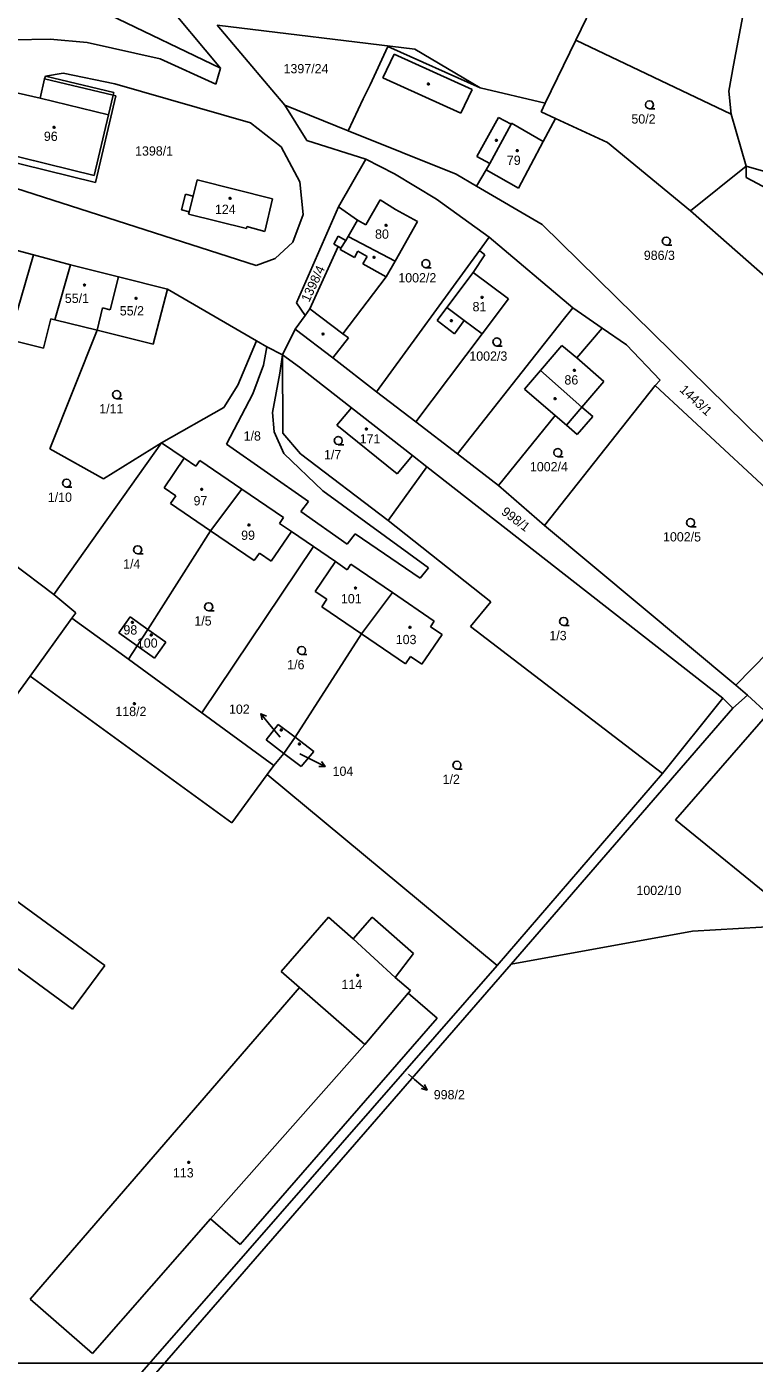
# Model space of a CAD drawing. Extents: x -852001 to -842497, y -1063614 to -1052182.
# Drawn here: x -849296.3 to -849163.1, y -1056500 to -1056255.4 of the extents above; entities that cross this region are included whole.
import ezdxf

# ---------------------------------------------------------------- set-up
doc = ezdxf.new("R2010")
doc.units = 0
for name, color, linetype in [('Default', 7, 'Continuous'), ('KLADY_ZMVM', 7, 'Continuous'), ('KN_HRANICE', 7, 'Continuous'), ('KN_KULTURY', 7, 'Continuous'), ('KN_PARCELY', 7, 'Continuous'), ('KN_SLUCKY', 7, 'Continuous')]:
    doc.layers.add(name, color=color, linetype=linetype)

# ---------------------------------------------------------------- blocks, each defined once
blk = doc.blocks.new('304')
at = {"layer": 'Default'}
blk.add_lwpolyline([(0, 0), (-0.38, 0.1), (-0.65, 0.37), (-0.75, 0.74), (-0.65, 1.11), (-0.38, 1.38), (-0.01, 1.48), (0.36, 1.38), (0.63, 1.11), (0.73, 0.73), (0.63, 0.35), (0.36, 0.08), (-0.02, -0.02), (0.98, -0.02)], dxfattribs=at)
blk = doc.blocks.new('NAHRADNI_SYMBOL')
at = {"layer": 'Default'}
blk.add_lwpolyline([(0.09, 0.15), (0.18, 0), (0.09, -0.15), (-0.09, -0.15), (-0.18, 0), (-0.09, 0.15), (0.09, 0.15)], dxfattribs=at)
blk = doc.blocks.new('10292')
at = {"layer": 'Default'}
blk.add_line((0, 3), (0, 0), dxfattribs=at)
blk.add_lwpolyline([(-0.5, 2), (0, 3), (0.5, 2)], dxfattribs=at)
blk = doc.blocks.new('402')
at = {"layer": 'Default'}
blk.add_lwpolyline([(0.09, 0.15), (0.18, 0), (0.09, -0.15), (-0.09, -0.15), (-0.18, 0), (-0.09, 0.15), (0.09, 0.15)], dxfattribs=at)

msp = doc.modelspace()

# ---------------------------------------------------------------- linework, layer by layer
at = {"layer": 'KLADY_ZMVM'}
msp.add_lwpolyline([(-849375, -1056500), (-848750, -1056500), (-848750, -1056000)], dxfattribs=at)
at = {"layer": 'KN_HRANICE'}
for p, q in [((-849279.99, -1056240.09), (-849260.83, -1056263.03)), ((-849187.73, -1056241.12), (-849195.81, -1056257.87)), ((-849166.92, -1056262.43), (-849164.8, -1056251.16)), ((-849281.15, -1056253.26), (-849260.83, -1056263.03)), ((-849261.46, -1056255.12), (-849257.13, -1056260.24)), ((-849261.46, -1056255.12), (-849225.25, -1056259.54)), ((-849298.81, -1056257.8), (-849292.01, -1056257.69)), ((-849292.01, -1056257.69), (-849285.23, -1056258.34)), ((-849285.23, -1056258.34), (-849271.88, -1056261.33)), ((-849257.13, -1056260.24), (-849251.43, -1056266.98)), ((-849230.23, -1056259.07), (-849233.42, -1056266.05)), ((-849230.23, -1056259.07), (-849213.31, -1056266.59)), ((-849225.25, -1056259.54), (-849213.31, -1056266.59)), ((-849195.81, -1056257.87), (-849201.39, -1056269.43)), ((-849195.81, -1056257.87), (-849167.34, -1056271.45)), ((-849271.88, -1056261.33), (-849261.72, -1056265.96)), ((-849167.78, -1056267.19), (-849166.92, -1056262.43)), ((-849293.85, -1056268.49), (-849293.05, -1056264.93)), ((-849292.89, -1056264.47), (-849293.05, -1056264.93)), ((-849292.89, -1056264.47), (-849289.64, -1056263.9)), ((-849280.38, -1056267.45), (-849292.89, -1056264.47)), ((-849289.64, -1056263.9), (-849280.17, -1056265.87)), ((-849261.72, -1056265.96), (-849260.83, -1056263.03)), ((-849297.86, -1056267.56), (-849293.85, -1056268.49)), ((-849280.52, -1056267.92), (-849280.38, -1056267.45)), ((-849280.17, -1056265.87), (-849255.38, -1056273.01)), ((-849251.43, -1056266.98), (-849249.09, -1056269.78)), ((-849233.42, -1056266.05), (-849234.71, -1056268.6)), ((-849201.39, -1056269.43), (-849213.31, -1056266.59)), ((-849167.34, -1056271.45), (-849167.78, -1056267.19)), ((-849283.7, -1056283.9), (-849280.01, -1056268.08)), ((-849280.01, -1056268.08), (-849280.52, -1056267.92)), ((-849249.09, -1056269.78), (-849245.03, -1056276.25)), ((-849249.09, -1056269.78), (-849237.45, -1056274.45)), ((-849234.71, -1056268.6), (-849237.45, -1056274.45)), ((-849201.39, -1056269.43), (-849202.16, -1056271.02)), ((-849202.16, -1056271.02), (-849199.51, -1056272.24)), ((-849201.75, -1056276.45), (-849199.51, -1056272.24)), ((-849199.51, -1056272.24), (-849189.99, -1056276.6)), ((-849167.34, -1056271.45), (-849164.6, -1056280.95)), ((-849255.38, -1056273.01), (-849249.72, -1056277.39)), ((-849237.45, -1056274.45), (-849217.67, -1056282.38)), ((-849249.72, -1056277.39), (-849246.35, -1056283.83)), ((-849245.03, -1056276.25), (-849234.23, -1056279.63)), ((-849206.29, -1056284.99), (-849201.75, -1056276.45)), ((-849189.99, -1056276.6), (-849174.78, -1056289.12)), ((-849254.33, -1056299.1), (-849321.06, -1056277.69)), ((-849307.26, -1056278.16), (-849283.7, -1056283.9)), ((-849239.22, -1056288.41), (-849234.23, -1056279.63)), ((-849234.23, -1056279.63), (-849228.99, -1056282.32)), ((-849228.99, -1056282.32), (-849221.32, -1056287)), ((-849213.98, -1056284.6), (-849212.18, -1056281.64)), ((-849212.18, -1056281.64), (-849206.29, -1056284.99)), ((-849174.78, -1056289.12), (-849164.6, -1056280.95)), ((-849164.6, -1056280.95), (-849143.72, -1056286.9)), ((-849164.6, -1056280.95), (-849164.59, -1056283.02)), ((-849265.86, -1056286.42), (-849265.11, -1056283.46)), ((-849265.11, -1056283.46), (-849251.31, -1056286.91)), ((-849246.35, -1056283.83), (-849245.71, -1056289.79)), ((-849217.67, -1056282.38), (-849213.98, -1056284.6)), ((-849213.98, -1056284.6), (-849201.97, -1056291.61)), ((-849150.22, -1056290.7), (-849164.59, -1056283.02)), ((-849267.99, -1056288.94), (-849267.27, -1056286.07)), ((-849267.27, -1056286.07), (-849265.86, -1056286.42)), ((-849252.72, -1056292.88), (-849251.31, -1056286.91)), ((-849231.64, -1056287.13), (-849234.22, -1056291.69)), ((-849231.64, -1056287.13), (-849228.79, -1056288.86)), ((-849221.32, -1056287), (-849211.67, -1056293.94)), ((-849266.58, -1056289.3), (-849267.99, -1056288.94)), ((-849266.69, -1056289.75), (-849266.58, -1056289.3)), ((-849246.94, -1056305.93), (-849239.22, -1056288.41)), ((-849239.22, -1056288.41), (-849235.78, -1056290.81)), ((-849228.79, -1056288.86), (-849224.8, -1056291.07)), ((-849174.78, -1056289.12), (-849146.16, -1056314.38)), ((-849266.69, -1056289.75), (-849256.11, -1056292.32)), ((-849256.11, -1056292.32), (-849256.03, -1056292)), ((-849256.03, -1056292), (-849252.72, -1056292.88)), ((-849245.71, -1056289.79), (-849247.6, -1056294.83)), ((-849237.48, -1056293.82), (-849235.78, -1056290.81)), ((-849234.22, -1056291.69), (-849235.78, -1056290.81)), ((-849224.8, -1056291.07), (-849228.88, -1056298.35)), ((-849161.41, -1056331.37), (-849201.97, -1056291.61)), ((-849240.1, -1056295.2), (-849239.29, -1056293.78)), ((-849239.29, -1056293.78), (-849237.9, -1056294.56)), ((-849237.9, -1056294.56), (-849237.48, -1056293.82)), ((-849211.67, -1056293.94), (-849213.44, -1056296.36)), ((-849211.67, -1056293.94), (-849196.32, -1056306.88)), ((-849295.08, -1056297.16), (-849299.89, -1056295.86)), ((-849247.6, -1056294.83), (-849250.85, -1056297.85)), ((-849244.48, -1056307.03), (-849239.28, -1056295.66)), ((-849240.1, -1056295.2), (-849239.28, -1056295.66)), ((-849213.44, -1056296.36), (-849232.27, -1056322.21)), ((-849212.44, -1056297.19), (-849213.44, -1056296.36)), ((-849288.31, -1056299), (-849295.08, -1056297.16)), ((-849291.17, -1056309.06), (-849288.31, -1056299)), ((-849288.31, -1056299), (-849279.52, -1056301.18)), ((-849250.85, -1056297.85), (-849254.33, -1056299.1)), ((-849228.88, -1056298.35), (-849230.49, -1056301.22)), ((-849214.56, -1056300.37), (-849212.44, -1056297.19)), ((-849281.07, -1056307.24), (-849279.52, -1056301.18)), ((-849279.52, -1056301.18), (-849270.57, -1056303.47)), ((-849230.49, -1056301.22), (-849238.43, -1056311.61)), ((-849208.12, -1056305.21), (-849214.56, -1056300.37)), ((-849270.57, -1056303.47), (-849273.15, -1056313.52)), ((-849270.57, -1056303.47), (-849254.26, -1056312.92)), ((-849246.94, -1056305.93), (-849245.37, -1056308.26)), ((-849208.12, -1056305.21), (-849212.96, -1056311.65)), ((-849293.26, -1056314.27), (-849291.9, -1056308.87)), ((-849291.9, -1056308.87), (-849291.17, -1056309.06)), ((-849283.45, -1056310.97), (-849291.17, -1056309.06)), ((-849283.45, -1056310.97), (-849282.44, -1056306.89)), ((-849282.44, -1056306.89), (-849281.07, -1056307.24)), ((-849247.18, -1056310.75), (-849245.37, -1056308.26)), ((-849245.37, -1056308.26), (-849244.48, -1056307.03)), ((-849217.45, -1056333.6), (-849198.14, -1056309.07)), ((-849196.32, -1056306.88), (-849198.14, -1056309.07)), ((-849190.95, -1056310.59), (-849196.32, -1056306.88)), ((-849310.53, -1056309.9), (-849293.26, -1056314.27)), ((-849292.1, -1056332.65), (-849283.45, -1056310.97)), ((-849273.15, -1056313.52), (-849283.45, -1056310.97)), ((-849249.52, -1056315.45), (-849247.18, -1056310.75)), ((-849240.27, -1056316.03), (-849247.18, -1056310.75)), ((-849238.43, -1056311.61), (-849237.42, -1056312.38)), ((-849212.96, -1056311.65), (-849225.06, -1056327.75)), ((-849195.6, -1056316.01), (-849190.95, -1056310.59)), ((-849186.5, -1056313.66), (-849190.95, -1056310.59)), ((-849254.26, -1056312.92), (-849257.7, -1056321.02)), ((-849254.26, -1056312.92), (-849252.37, -1056314.02)), ((-849252.95, -1056317.34), (-849252.37, -1056314.02)), ((-849252.37, -1056314.02), (-849249.52, -1056315.45)), ((-849237.42, -1056312.38), (-849240.27, -1056316.03)), ((-849180.36, -1056320.1), (-849186.5, -1056313.66)), ((-849249.52, -1056315.45), (-849250, -1056318.83)), ((-849249.41, -1056329.82), (-849249.52, -1056315.45)), ((-849249.52, -1056315.45), (-849246.38, -1056317.74)), ((-849232.27, -1056322.21), (-849240.27, -1056316.03)), ((-849195.6, -1056316.01), (-849190.65, -1056320.37)), ((-849254.93, -1056322.6), (-849252.95, -1056317.34)), ((-849250, -1056318.83), (-849251.32, -1056325.99)), ((-849246.38, -1056317.74), (-849236.86, -1056325.16)), ((-849257.7, -1056321.02), (-849260.26, -1056325.11)), ((-849201.5, -1056346.7), (-849181.26, -1056321.09)), ((-849194.67, -1056325.05), (-849190.65, -1056320.37)), ((-849181.26, -1056321.09), (-849180.36, -1056320.1)), ((-849181.26, -1056321.09), (-849145.42, -1056354.4)), ((-849259.75, -1056331.81), (-849254.93, -1056322.6)), ((-849225.06, -1056327.75), (-849232.27, -1056322.21)), ((-849260.26, -1056325.11), (-849271.64, -1056331.55)), ((-849251.32, -1056325.99), (-849251.01, -1056329.53)), ((-849239.52, -1056328.34), (-849236.86, -1056325.16)), ((-849236.86, -1056325.16), (-849225.69, -1056333.89)), ((-849194.67, -1056325.05), (-849192.7, -1056326.75)), ((-849228.48, -1056337.23), (-849239.52, -1056328.34)), ((-849217.45, -1056333.6), (-849225.06, -1056327.75)), ((-849209.96, -1056339.35), (-849199.56, -1056326.59)), ((-849197.51, -1056328.35), (-849199.56, -1056326.59)), ((-849195.53, -1056330.05), (-849197.51, -1056328.35)), ((-849192.7, -1056326.75), (-849195.53, -1056330.05)), ((-849251.01, -1056329.53), (-849249.23, -1056333.55)), ((-849246.19, -1056333.59), (-849249.41, -1056329.82)), ((-849282.25, -1056338.14), (-849292.1, -1056332.65)), ((-849291.34, -1056359.34), (-849271.64, -1056331.55)), ((-849271.64, -1056331.55), (-849282.25, -1056338.14)), ((-849271.64, -1056331.55), (-849267.48, -1056334.39)), ((-849244.73, -1056342.28), (-849259.75, -1056331.81)), ((-849249.23, -1056333.55), (-849242.11, -1056340.33)), ((-849230.16, -1056345.77), (-849246.19, -1056333.59)), ((-849209.96, -1056339.35), (-849217.45, -1056333.6)), ((-849267.48, -1056334.39), (-849271.16, -1056339.78)), ((-849265.33, -1056335.85), (-849267.48, -1056334.39)), ((-849264.6, -1056334.81), (-849265.33, -1056335.85)), ((-849264.6, -1056334.81), (-849256.96, -1056340.03)), ((-849223.07, -1056335.94), (-849230.16, -1056345.77)), ((-849225.69, -1056333.89), (-849228.48, -1056337.23)), ((-849223.07, -1056335.94), (-849225.69, -1056333.89)), ((-849223.07, -1056335.94), (-849168.88, -1056378.32)), ((-849271.16, -1056339.78), (-849269.01, -1056341.24)), ((-849262.65, -1056347.66), (-849256.96, -1056340.03)), ((-849256.96, -1056340.03), (-849249.3, -1056345.26)), ((-849242.11, -1056340.33), (-849222.76, -1056354.44)), ((-849201.5, -1056346.7), (-849209.96, -1056339.35)), ((-849269.01, -1056341.24), (-849269.98, -1056342.65)), ((-849269.98, -1056342.65), (-849262.65, -1056347.66)), ((-849246.11, -1056344.16), (-849244.73, -1056342.28)), ((-849250.02, -1056346.33), (-849249.3, -1056345.26)), ((-849237.68, -1056350.14), (-849246.11, -1056344.16)), ((-849230.16, -1056345.77), (-849211.36, -1056360.66)), ((-849262.65, -1056347.66), (-849274.12, -1056365.74)), ((-849262.65, -1056347.66), (-849254.67, -1056353.12)), ((-849251.57, -1056353.21), (-849247.87, -1056347.82)), ((-849247.87, -1056347.82), (-849250.02, -1056346.33)), ((-849243.84, -1056350.56), (-849247.87, -1056347.82)), ((-849236.2, -1056348.24), (-849237.68, -1056350.14)), ((-849224.27, -1056356.34), (-849236.2, -1056348.24)), ((-849201.5, -1056346.7), (-849166.49, -1056375.89)), ((-849264.25, -1056380.97), (-849243.84, -1056350.56)), ((-849243.84, -1056350.56), (-849239.82, -1056353.29)), ((-849254.67, -1056353.12), (-849253.72, -1056351.73)), ((-849253.72, -1056351.73), (-849251.57, -1056353.21)), ((-849291.34, -1056359.34), (-849299.09, -1056353.44)), ((-849239.82, -1056353.29), (-849243.49, -1056358.79)), ((-849237.67, -1056354.78), (-849239.82, -1056353.29)), ((-849236.96, -1056353.76), (-849237.67, -1056354.78)), ((-849229.36, -1056358.98), (-849236.96, -1056353.76)), ((-849222.76, -1056354.44), (-849224.27, -1056356.34)), ((-849147.47, -1056356.49), (-849166.49, -1056375.89)), ((-849287.35, -1056362.68), (-849291.34, -1056359.34)), ((-849243.49, -1056358.79), (-849241.35, -1056360.18)), ((-849241.35, -1056360.18), (-849242.29, -1056361.57)), ((-849235.05, -1056366.54), (-849229.36, -1056358.98)), ((-849221.74, -1056364.19), (-849229.36, -1056358.98)), ((-849288.04, -1056363.64), (-849287.35, -1056362.68)), ((-849242.29, -1056361.57), (-849235.05, -1056366.54)), ((-849211.36, -1056360.66), (-849215.1, -1056365.17)), ((-849288.04, -1056363.64), (-849295.68, -1056374.24)), ((-849277.71, -1056371.17), (-849288.04, -1056363.64)), ((-849277.39, -1056363.43), (-849279.45, -1056366.33)), ((-849274.12, -1056365.74), (-849277.39, -1056363.43)), ((-849221.74, -1056364.19), (-849222.41, -1056365.22)), ((-849222.41, -1056365.22), (-849220.26, -1056366.67)), ((-849215.1, -1056365.17), (-849179.95, -1056392.09)), ((-849279.45, -1056366.33), (-849276.09, -1056368.72)), ((-849274.12, -1056365.74), (-849276.09, -1056368.72)), ((-849270.88, -1056368.05), (-849274.12, -1056365.74)), ((-849235.05, -1056366.54), (-849247.17, -1056385.43)), ((-849235.05, -1056366.54), (-849227, -1056372.04)), ((-849220.26, -1056366.67), (-849223.96, -1056372.1)), ((-849276.09, -1056368.72), (-849277.71, -1056371.17)), ((-849276.09, -1056368.72), (-849272.9, -1056370.99)), ((-849272.9, -1056370.99), (-849270.88, -1056368.05)), ((-849264.25, -1056380.97), (-849277.71, -1056371.17)), ((-849226.06, -1056370.67), (-849227, -1056372.04)), ((-849223.96, -1056372.1), (-849226.06, -1056370.67)), ((-849295.68, -1056374.24), (-849308.52, -1056391.92)), ((-849258.75, -1056401.09), (-849295.68, -1056374.24)), ((-849166.49, -1056375.89), (-849164.34, -1056377.76)), ((-849207.62, -1056426.96), (-849167.05, -1056380.13)), ((-849179.95, -1056392.09), (-849168.88, -1056378.32)), ((-849168.88, -1056378.32), (-849167.05, -1056380.13)), ((-849167.05, -1056380.13), (-849164.34, -1056377.76)), ((-849160.67, -1056381.14), (-849164.34, -1056377.76)), ((-849251.09, -1056390.6), (-849264.25, -1056380.97)), ((-849177.57, -1056400.57), (-849160.67, -1056381.14)), ((-849252.49, -1056385.93), (-849250.27, -1056383.09)), ((-849250.27, -1056383.09), (-849247.17, -1056385.43)), ((-849249.26, -1056388.39), (-849252.49, -1056385.93)), ((-849249.26, -1056388.39), (-849247.17, -1056385.43)), ((-849247.17, -1056385.43), (-849243.74, -1056388.04)), ((-849251.09, -1056390.6), (-849249.26, -1056388.39)), ((-849246.07, -1056390.82), (-849249.26, -1056388.39)), ((-849243.74, -1056388.04), (-849246.07, -1056390.82)), ((-849258.75, -1056401.09), (-849252.32, -1056392.28)), ((-849252.32, -1056392.28), (-849251.09, -1056390.6)), ((-849252.32, -1056392.28), (-849210.21, -1056427.21)), ((-849210.21, -1056427.21), (-849179.95, -1056392.09)), ((-849177.57, -1056400.57), (-849153.92, -1056419.76)), ((-849305.54, -1056410.02), (-849282.02, -1056427.2)), ((-849287.91, -1056435.18), (-849311.74, -1056417.78)), ((-849249.75, -1056428.29), (-849241.09, -1056418.38)), ((-849241.09, -1056418.38), (-849236.55, -1056422.35)), ((-849236.55, -1056422.35), (-849233.09, -1056418.39)), ((-849225.51, -1056425.01), (-849233.09, -1056418.39)), ((-849174.42, -1056420.91), (-849207.62, -1056426.96)), ((-849153.92, -1056419.76), (-849174.42, -1056420.91)), ((-849225.51, -1056425.01), (-849228.87, -1056429.39)), ((-849210.21, -1056427.21), (-849289.39, -1056517.79)), ((-849289.35, -1056520.97), (-849207.62, -1056426.96)), ((-849282.02, -1056427.2), (-849287.91, -1056435.18)), ((-849246.39, -1056431.22), (-849249.75, -1056428.29)), ((-849295.7, -1056488.26), (-849246.39, -1056431.22)), ((-849234.42, -1056441.65), (-849246.39, -1056431.22)), ((-849228.87, -1056429.39), (-849226.07, -1056431.8)), ((-849234.42, -1056441.65), (-849226.46, -1056432.26)), ((-849226.46, -1056432.26), (-849226.07, -1056431.8)), ((-849221.16, -1056436.85), (-849226.46, -1056432.26)), ((-849257.24, -1056478.3), (-849221.16, -1056436.85)), ((-849284.26, -1056498.23), (-849262.65, -1056473.57)), ((-849262.65, -1056473.57), (-849257.24, -1056478.3)), ((-849295.7, -1056488.26), (-849284.26, -1056498.23))]:
    msp.add_line(p, q, dxfattribs=at)
at = {"layer": 'KN_PARCELY'}
for p, q in [((-849249.93, -1056385.45), (-849251.54, -1056383.48)), ((-849246.35, -1056388.48), (-849244.39, -1056389.46)), ((-849226.43, -1056447.1), (-849225.32, -1056448.05))]:
    msp.add_line(p, q, dxfattribs=at)
at = {"layer": 'KN_SLUCKY'}
for p, q in [((-849229.04, -1056260.47), (-849231.13, -1056264.79)), ((-849229.04, -1056260.47), (-849214.76, -1056266.9)), ((-849293.05, -1056264.93), (-849280.52, -1056267.92)), ((-849216.86, -1056271.25), (-849231.13, -1056264.79)), ((-849214.76, -1056266.9), (-849216.86, -1056271.25)), ((-849293.85, -1056268.49), (-849281.34, -1056271.54)), ((-849280.52, -1056267.92), (-849281.34, -1056271.54)), ((-849281.34, -1056271.54), (-849283.98, -1056282.62)), ((-849209.93, -1056272.01), (-849213.92, -1056279.18)), ((-849207.65, -1056273.25), (-849209.93, -1056272.01)), ((-849211.54, -1056280.46), (-849207.65, -1056273.25)), ((-849207.55, -1056273.07), (-849207.65, -1056273.25)), ((-849201.75, -1056276.45), (-849207.55, -1056273.07)), ((-849283.98, -1056282.62), (-849305.79, -1056277.31)), ((-849213.92, -1056279.18), (-849211.54, -1056280.46)), ((-849211.54, -1056280.46), (-849212.18, -1056281.64)), ((-849265.86, -1056286.42), (-849266.58, -1056289.3)), ((-849237.48, -1056293.82), (-849228.88, -1056298.35)), ((-849239.28, -1056295.66), (-849238.79, -1056295.94)), ((-849238.93, -1056296.18), (-849238.79, -1056295.94)), ((-849236.33, -1056297.65), (-849238.93, -1056296.18)), ((-849238.79, -1056295.94), (-849237.9, -1056294.56)), ((-849235.68, -1056296.5), (-849236.33, -1056297.65)), ((-849234.01, -1056297.45), (-849235.68, -1056296.5)), ((-849295.08, -1056297.16), (-849297.98, -1056307.31)), ((-849234.77, -1056298.8), (-849234.01, -1056297.45)), ((-849230.49, -1056301.22), (-849234.77, -1056298.8)), ((-849214.56, -1056300.37), (-849219.4, -1056306.81)), ((-849244.48, -1056307.03), (-849238.43, -1056311.61)), ((-849219.4, -1056306.81), (-849221.2, -1056309.2)), ((-849221.2, -1056309.2), (-849218.01, -1056311.6)), ((-849219.4, -1056306.81), (-849216.21, -1056309.21)), ((-849218.01, -1056311.6), (-849216.21, -1056309.21)), ((-849216.21, -1056309.21), (-849212.96, -1056311.65)), ((-849198.33, -1056313.77), (-849202.26, -1056318.34)), ((-849198.33, -1056313.77), (-849195.6, -1056316.01)), ((-849202.26, -1056318.34), (-849205.19, -1056321.75)), ((-849194.67, -1056325.05), (-849202.26, -1056318.34)), ((-849199.56, -1056326.59), (-849205.19, -1056321.75)), ((-849197.51, -1056328.35), (-849194.67, -1056325.05)), ((-849228.87, -1056429.39), (-849236.55, -1056422.35)), ((-849262.65, -1056473.57), (-849234.42, -1056441.65))]:
    msp.add_line(p, q, dxfattribs=at)

# ---------------------------------------------------------------- block references
at = {"layer": 'KN_KULTURY'}
for name, p in [('402', (-849222.78, -1056265.88)), ('304', (-849182.3, -1056270.45)), ('402', (-849291.32, -1056273.83)), ('402', (-849210.34, -1056276.22)), ('402', (-849206.51, -1056278.1)), ('402', (-849259.1, -1056286.8)), ('402', (-849230.54, -1056291.76)), ('304', (-849179.22, -1056295.4)), ('402', (-849232.74, -1056297.62)), ('304', (-849223.23, -1056299.52)), ('402', (-849285.74, -1056302.7)), ('402', (-849276.31, -1056305.12)), ('402', (-849212.96, -1056304.95)), ('402', (-849218.56, -1056309.23)), ('402', (-849242.08, -1056311.66)), ('304', (-849210.23, -1056313.85)), ('402', (-849196.05, -1056318.28)), ('304', (-849279.84, -1056323.49)), ('402', (-849199.59, -1056323.47)), ('304', (-849239.27, -1056331.89)), ('402', (-849234.14, -1056329.06)), ('304', (-849199.1, -1056334.09)), ('304', (-849289.02, -1056339.67)), ('402', (-849264.29, -1056340.08)), ('304', (-849174.77, -1056346.92)), ('402', (-849255.65, -1056346.59)), ('304', (-849276, -1056351.88)), ('402', (-849236.13, -1056358.15)), ('304', (-849263, -1056362.3)), ('402', (-849276.97, -1056364.39)), ('402', (-849226.17, -1056365.32)), ('304', (-849198.01, -1056364.99)), ('402', (-849273.52, -1056366.71)), ('304', (-849246, -1056370.3)), ('NAHRADNI_SYMBOL', (-849276.61, -1056379.29)), ('402', (-849249.73, -1056384.11)), ('402', (-849246.4, -1056386.67)), ('304', (-849217.56, -1056391.28)), ('402', (-849235.73, -1056428.99)), ('402', (-849266.66, -1056463.26))]:
    msp.add_blockref(name, p, dxfattribs=at)
at = {"layer": 'KN_PARCELY'}
for p, rotation in [((-849251.54, -1056383.48), 39.304905), ((-849244.39, -1056389.46), -116.66482400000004), ((-849225.32, -1056448.05), -130.53040299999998)]:
    msp.add_blockref('10292', p, dxfattribs=dict(at, rotation=rotation))

# ---------------------------------------------------------------- texts
for s, height, p in [('1397/24', 1.7, (-849249.3, -1056263.95)), ('50/2', 1.7, (-849185.62, -1056273.15)), ('96', 1.7, (-849293.18, -1056276.32)), ('1398/1', 1.7, (-849276.48, -1056279.01)), ('79', 1.7, (-849208.42, -1056280.71)), ('124', 1.7, (-849261.86, -1056289.68)), ('80', 1.7, (-849232.55, -1056294.22)), ('986/3', 1.7, (-849183.35, -1056298.1)), ('1002/2', 1.7, (-849228.29, -1056302.22)), ('55/1', 1.7, (-849289.34, -1056305.98)), ('55/2', 1.7, (-849279.28, -1056308.26)), ('81', 1.7, (-849214.7, -1056307.5)), ('1002/3', 1.7, (-849215.29, -1056316.55)), ('86', 1.7, (-849197.88, -1056320.9)), ('1/11', 1.7, (-849283.04, -1056326.19)), ('1/8', 1.7, (-849256.61, -1056331.16)), ('171', 1.7, (-849235.36, -1056331.69)), ('1/7', 1.7, (-849241.9, -1056334.59)), ('1002/4', 1.7, (-849204.2, -1056336.79)), ('1/10', 1.7, (-849292.46, -1056342.37)), ('97', 1.7, (-849265.78, -1056343.02)), ('99', 1.7, (-849257.06, -1056349.33)), ('1002/5', 1.7, (-849179.83, -1056349.62)), ('1/4', 1.7, (-849278.67, -1056354.58)), ('101', 1.7, (-849238.8, -1056360.94)), ('98', 1.7, (-849278.61, -1056366.65)), ('1/5', 1.7, (-849265.63, -1056365)), ('100', 1.7, (-849276.15, -1056369.05)), ('103', 1.7, (-849228.76, -1056368.41)), ('1/3', 1.7, (-849200.64, -1056367.69)), ('1/6', 1.7, (-849248.63, -1056373)), ('118/2', 1.7, (-849280.09, -1056381.57)), ('102', 1.7, (-849259.29, -1056381.16)), ('102', 0.1, (-849250.08, -1056385.45)), ('104', 0.1, (-849246.5, -1056388.48)), ('104', 1.7, (-849240.32, -1056392.51)), ('1/2', 1.7, (-849220.19, -1056393.98)), ('1002/10', 1.7, (-849184.7, -1056414.32)), ('114', 1.7, (-849238.69, -1056431.51)), ('998/2', 0.1, (-849226.67, -1056447.1)), ('998/2', 1.7, (-849221.8, -1056451.7)), ('113', 1.7, (-849269.55, -1056466))]:
    msp.add_text(s, height=height, dxfattribs=at).set_placement(p)
for s, rotation, p in [('1398/4', 64.859, (-849244.62, -1056305.95)), ('1443/1', 317.189, (-849176.92, -1056322.03)), ('998/1', 323.205, (-849209.57, -1056344.51))]:
    msp.add_text(s, height=1.7, rotation=rotation, dxfattribs=at).set_placement(p)

doc.saveas('drawing.dxf')
